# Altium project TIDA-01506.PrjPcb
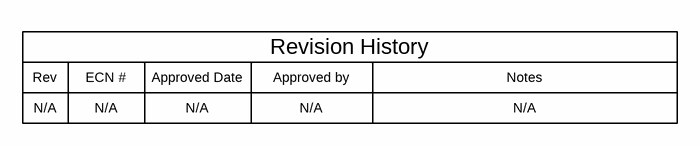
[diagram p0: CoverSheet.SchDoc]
CopyrightYear: 2017; EVM_orderable: N/A; PCB_Layout: Sandeep Tallada; PCB_Rev: E1; PRJ_Customer: Public Release; PRJ_Engineer: Sandeep Tallada; PRJ_Number: TIDA-01506; PRJ_Title: Reference Design for Automotive, Proportional-Solenoid Current Sensor; SCH_Rev: E1; TechSupport: http://www.ti.com/support; TID: TIDA-01506
3 sheets, 35 parts. Net scope: flat (ports and power ports of the same name join across sheets).
Board file: TIDA-01506_PCBLayout.PcbDoc
Sheets:
  CoverSheet.SchDoc
  EVM_Hardware.SchDoc
  TIDA-01506_Schematics.SchDoc

## Sheet CoverSheet.SchDoc
size 431 x 279 mm; Date: Not shown in title block; ApprovedBy: Not shown in title block; CheckedBy: Not shown in title block; Author: Not shown in title block; CompanyName: Not shown in title block; Engineer: Not shown in title block; Organization: Not shown in title block; Address1: Not shown in title block; Address2: Not shown in title block; Address3: Not shown in title block; Address4: Not shown in title block; DocumentNumber: 1; Revision: Use project parameter SCH_Rev; SheetNumber: 1; SheetTotal: 3; PageSetup: Record=PageOptions¦CenterHorizontal=True¦CenterVertical=True¦PrintScale=1.00¦XCorrection=1.00¦YCorrection=1.00¦PrintKind=0¦BorderSize=5000000¦LeftOffset=0¦BottomOffset=0¦Orientation=2¦PaperLength=1000¦PaperWidth=1000¦Scale=100¦PaperSource=15¦PrintQuality=600¦MediaType=1¦DitherType=10¦PaperKind=Letter¦PrintScaleMode=1

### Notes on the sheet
- Rev
- N/A
- ECN #
- Approved Date
- Approved by
- Revision History
- Notes

## Sheet EVM_Hardware.SchDoc
size 431 x 279 mm; Date: Not shown in title block; ApprovedBy: Not shown in title block; CheckedBy: Not shown in title block; Author: Not shown in title block; CompanyName: Not shown in title block; Engineer: Not shown in title block; Organization: Not shown in title block; Address1: Not shown in title block; Address2: Not shown in title block; Address3: Not shown in title block; Address4: Not shown in title block; DocumentNumber: 1; Revision: Use project parameter SCH_Rev; SheetNumber: 3; SheetTotal: 3; PageSetup: Record=PageOptions¦CenterHorizontal=True¦CenterVertical=True¦PrintScale=1.00¦XCorrection=1.00¦YCorrection=1.00¦PrintKind=0¦BorderSize=5000000¦LeftOffset=0¦BottomOffset=0¦Orientation=2¦PaperLength=1000¦PaperWidth=1000¦Scale=100¦PaperSource=15¦PrintQuality=600¦MediaType=1¦DitherType=10¦PaperKind=Letter¦PrintScaleMode=1
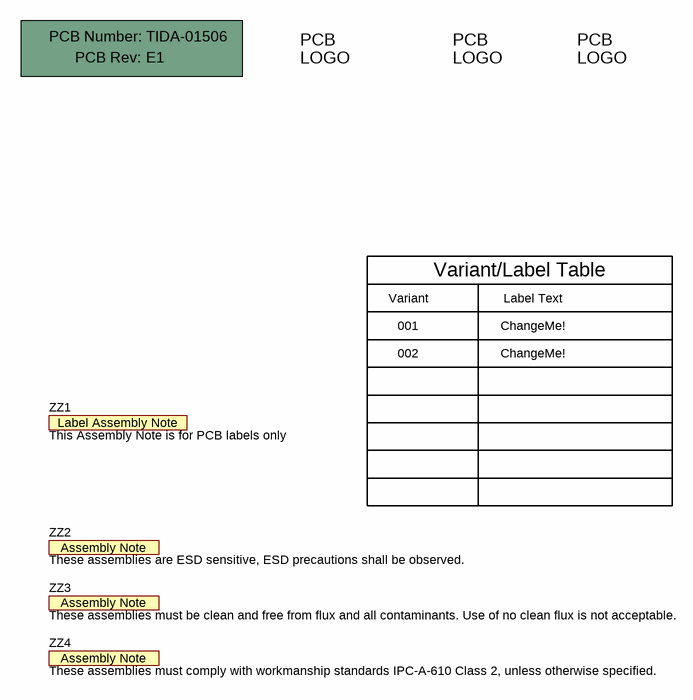
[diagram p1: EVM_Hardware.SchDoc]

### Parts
!PCB  Printed Circuit Board  (value not drawn)  (mechanical)
Logo1  Texas Instruments  [TI_Symbol_Overlay_Small]  (value not drawn)  (no BOM)
Logo2  Pb-Free Symbol  [Pb-Free_Overlay_Small]  (value not drawn)  (no BOM)
Logo3  FCC disclaimer  [FCC_disclaimer]  (value not drawn)  (no BOM)
ZZ1  This Assembly Note is for PCB labels only  [AssemblyNoteLabel]  (no BOM)
ZZ2  These assemblies are ESD sensitive, ESD precautions shall be observed.  [AssemblyNote]  (no BOM)
ZZ3  These assemblies must be clean and free from flux and all contaminants. Use of no clean flux is not acceptable.  [AssemblyNote]  (no BOM)
ZZ4  These assemblies must comply with workmanship standards IPC-A-610 Class 2, unless otherwise specified.  [AssemblyNote]  (no BOM)

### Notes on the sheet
- Variant
- Variant/Label Table
- Label Text
- 001
- 002
- ChangeMe!

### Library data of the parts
!PCB = PCB: Manufacturer: Any; PartNumber: TIDA-01506; SymbolCreator: a0412235
Logo1 = TI_Logo: Texas Instrument Corporate Signature; SymbolCreator: a0412235
Logo2 = Pb-Free: SymbolCreator: a0412235
Logo3 = FCC_disclaimer: SymbolCreator: a0412235
ZZ1 = AssemblyNoteLabel: SymbolCreator: a0412235
ZZ2-ZZ4 = AssemblyNote: SymbolCreator: codlsc

## Sheet TIDA-01506_Schematics.SchDoc
size 431 x 279 mm; Date: Not shown in title block; ApprovedBy: Not shown in title block; CheckedBy: Not shown in title block; Author: Not shown in title block; CompanyName: Not shown in title block; DrawnBy: Sandeep Tallada; Engineer: Sandeep Tallada; Organization: Not shown in title block; Address1: Not shown in title block; Address2: Not shown in title block; Address3: Not shown in title block; Address4: Not shown in title block; DocumentNumber: 1; Revision: Use project parameter SCH_Rev; SheetNumber: 2; SheetTotal: 3; PageSetup: Record=PageOptions¦CenterHorizontal=True¦CenterVertical=True¦PrintScale=0.62¦XCorrection=1.00¦YCorrection=1.00¦PrintKind=0¦BorderSize=5000000¦LeftOffset=0¦BottomOffset=0¦Orientation=2¦PaperLength=2794¦PaperWidth=2159¦Scale=100¦PaperSource=7¦PrintQuality=600¦MediaType=1¦DitherType=10¦PrintScaleMode=1¦PaperKind=8 1/2x11¦PaperIndex=1
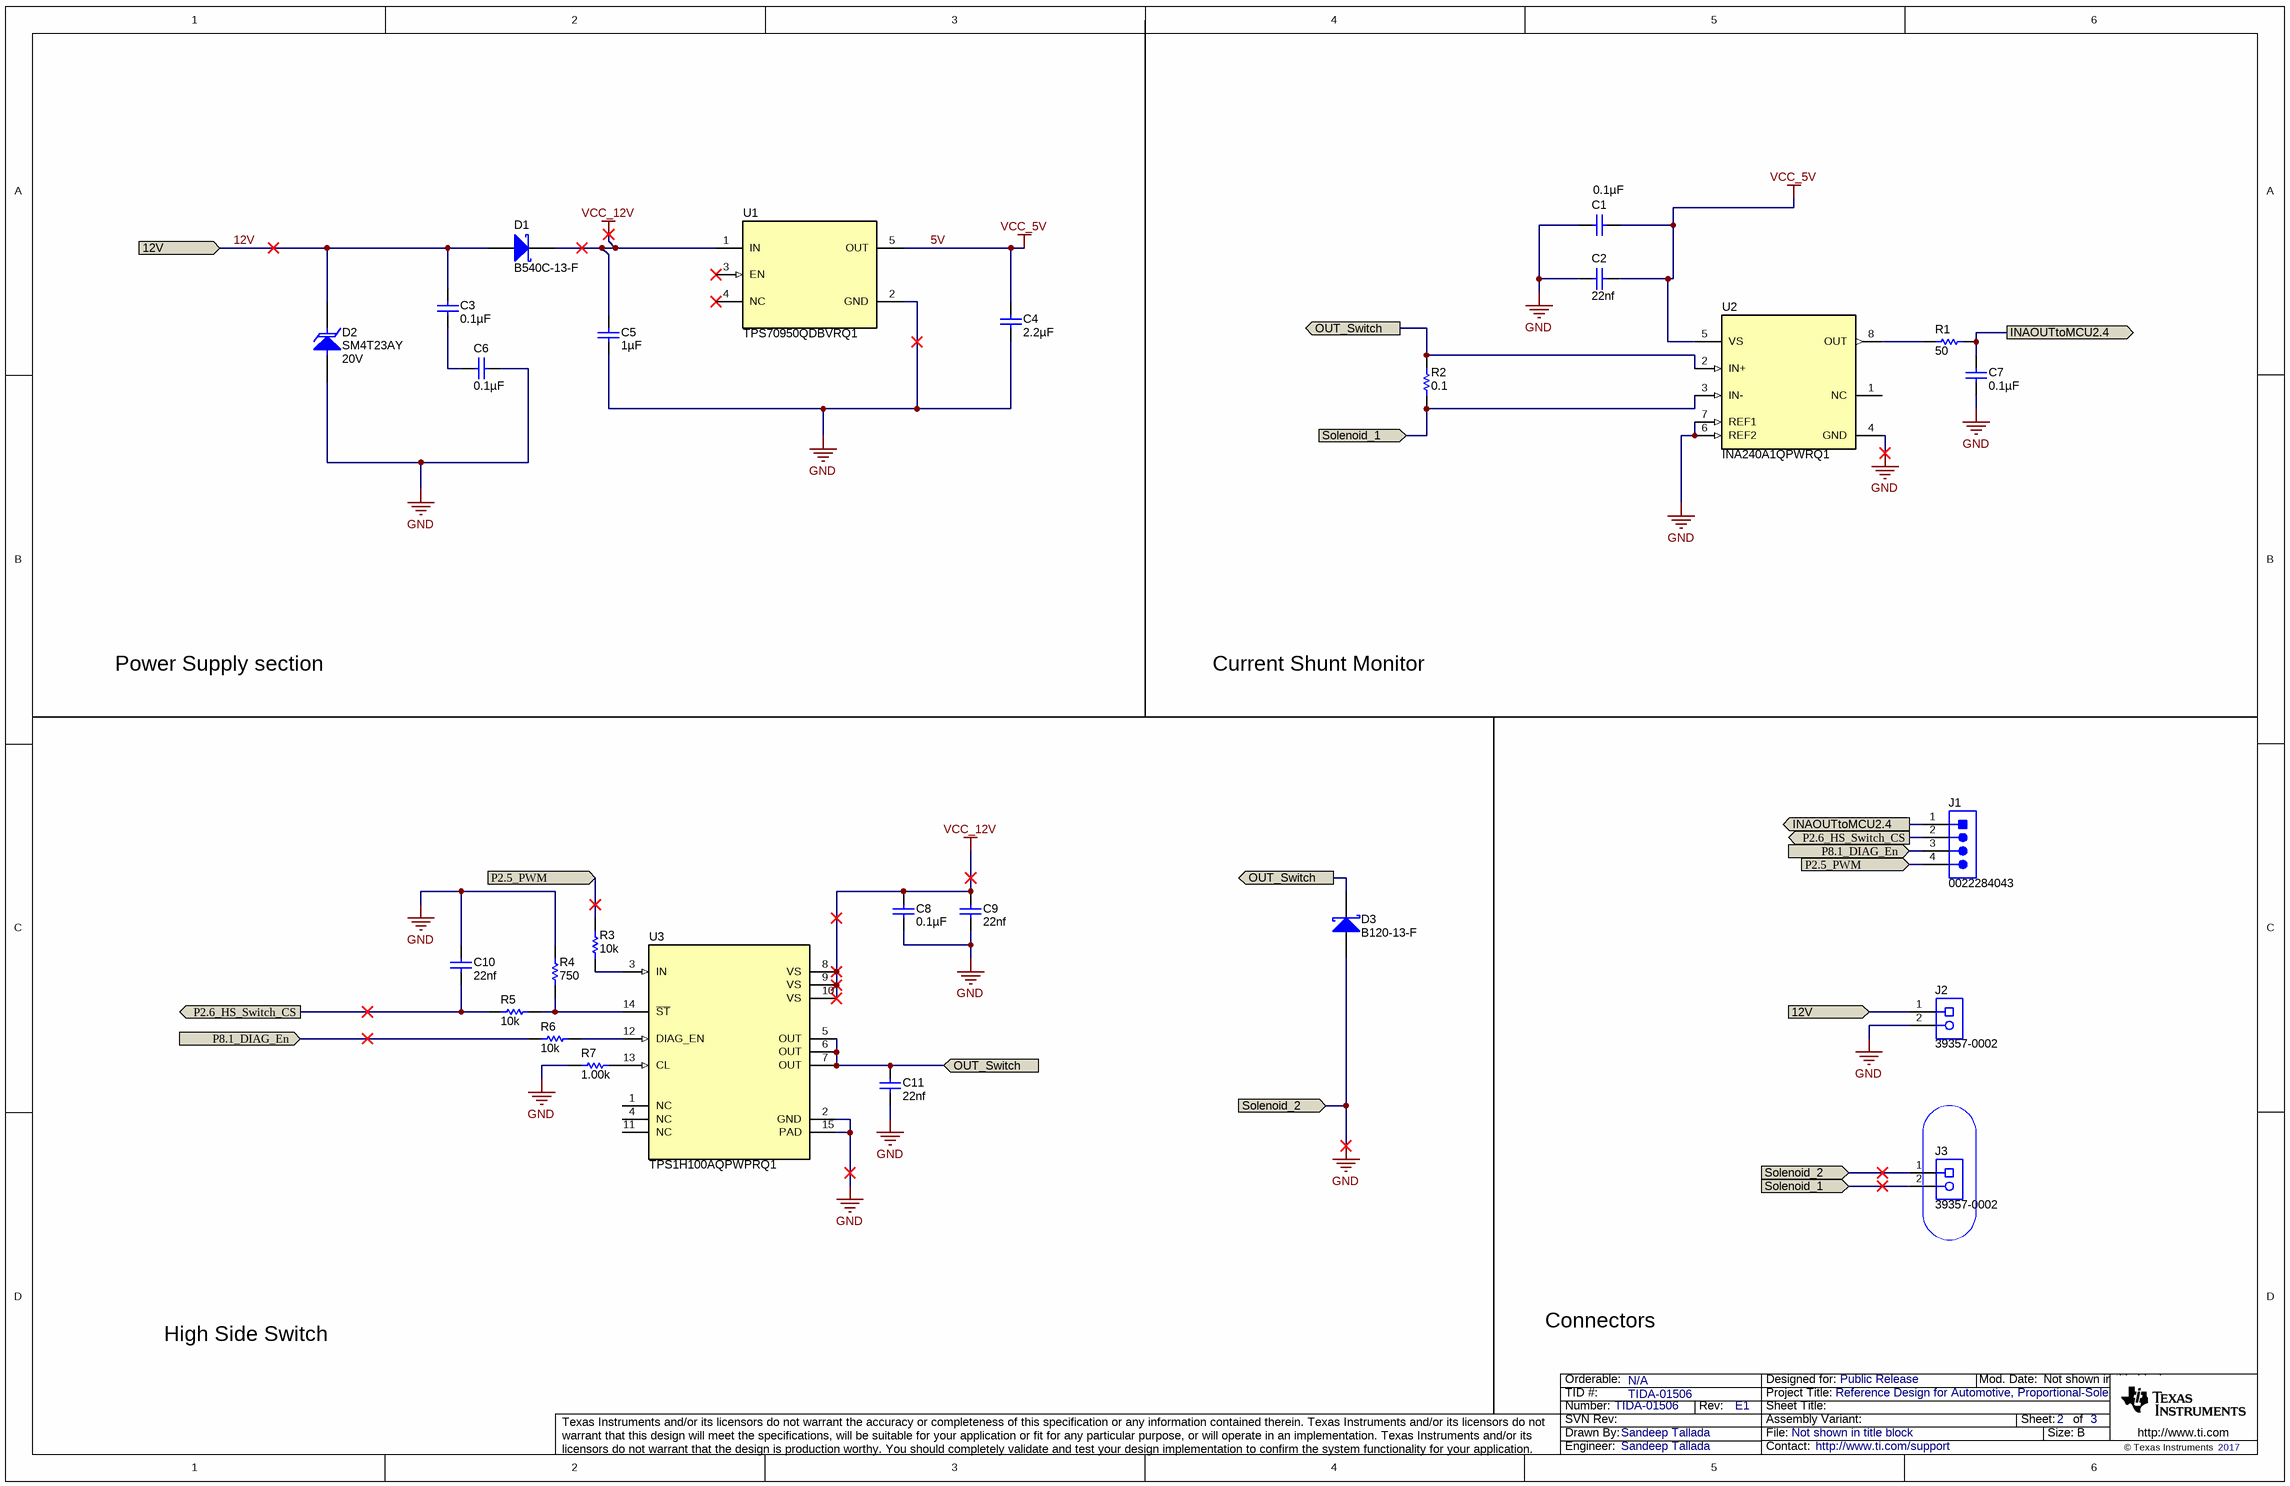
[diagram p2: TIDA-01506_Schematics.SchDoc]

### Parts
C1  ValueDisplayed: 0.1µF  [0603S]  (hidden comment: 0603YC104JAT2A)
C2  ValueDisplayed: 22nf  [0603S]  (hidden comment: CGA3E1X7R1V105K080AC)
C3  ValueDisplayed: 0.1µF  [0603S]  (hidden comment: GRM188R72A104KA35J)
C4  ValueDisplayed: 2.2µF  [0603S]  (hidden comment: GRM188Z71C225KE43)
C5  ValueDisplayed: 1µF  [0603S]  (hidden comment: CGA3E1X7R1V105K080AC)
C6  ValueDisplayed: 0.1µF  [0603S]  (hidden comment: GRM188R72A104KA35J)
C7  ValueDisplayed: 0.1µF  [0603S]  (hidden comment: 0603YC104JAT2A)
C8  ValueDisplayed: 0.1µF  [0603S]  (hidden comment: 0603YC104JAT2A)
C9  ValueDisplayed: 22nf  [0603S]  (hidden comment: CGA3E1X7R1V105K080AC)
C10  ValueDisplayed: 22nf  [0603S]  (hidden comment: CGA3E1X7R1V105K080AC)
C11  ValueDisplayed: 22nf  [0603S]  (hidden comment: CGA3E1X7R1V105K080AC)
D1  B540C-13-F  [SMC]
D2  SM4T23AY  value 20V  [SMA]
D3  B120-13-F  [SMA]
J1  0022284043  [Molex_0022284043]
J2  39357-0002  [Molex_39357-0002]
J3  39357-0002  [Molex_39357-0002]
R1  ValueDisplayed: 50  [0603S]  (hidden comment: FC0603E50R0BTBST1)
R2  value 0.1  [1206]  (hidden comment: UR73V2BTTDR100F)
R3  ValueDisplayed: 10k  [0603S]  (hidden comment: CRCW060310K0JNEA)
R4  ValueDisplayed: 750  [0805]  (hidden comment: CRCW0805750RJNEA)
R5  ValueDisplayed: 10k  [0603S]  (hidden comment: CRCW060310K0JNEA)
R6  ValueDisplayed: 10k  [0603S]  (hidden comment: CRCW060310K0JNEA)
R7  ValueDisplayed: 1.00k  [0805M]  (hidden comment: CRCW08051K00FKEA)
U1  TPS70950QDBVRQ1  [DBV0005A_N]
U2  INA240A1QPWRQ1  [PW0008A_N]
U3  TPS1H100AQPWPRQ1  [PWP0014F_N]

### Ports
12V (in), INAOUTtoMCU2.4 (out), OUT_Switch, P2.5_PWM (in), P2.6_HS_Switch_CS, P8.1_DIAG_En (in), Solenoid_1 (in), Solenoid_2 (in)

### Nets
5V: C1.2 C2.2 C4.1 U1.5(OUT) U2.5(VS)  [also labelled VCC_5V]
GND: C1.1 C2.1 C4.2 C5.1 C6.2 C7.2 C8.1 C9.1 C10.2 C11.1 D2.2(A) D3.2(A) J2.2 J3.1 R4.2 R7.1 U1.2(GND) U2.4(GND) U2.6(REF2) U2.7(REF1) U3.2(GND) U3.15(PAD) ; port Solenoid_2
VCC_12V: C5.2 C8.2 C9.2 D1.1(K) U1.1(IN) U3.8(VS) U3.9(VS) U3.10(VS)
12V: C3.1 D1.2(A) D2.1(K) J2.1 ; port 12V
INAOUTtoMCU2.4: C7.1 J1.1 R1.2 ; port INAOUTtoMCU2.4
OUT_Switch: C11.2 D3.1(K) R2.2 U2.2(IN+) U3.5(OUT) U3.6(OUT) U3.7(OUT) ; port OUT_Switch
P2.5_PWM: J1.4 R3.2 ; port P2.5_PWM
P2.6_HS_Switch_CS: C10.1 J1.2 R5.1 ; port P2.6_HS_Switch_CS
P8.1_DIAG_En: J1.3 R6.1 ; port P8.1_DIAG_En
Solenoid_1: J3.2 R2.1 U2.3(IN-) ; port Solenoid_1
NetC3_2: C3.2 C6.1
NetR1_1: R1.1 U2.8(OUT)
NetR3_1: R3.1 U3.3(IN)
NetR4_1: R4.1 R5.2 U3.14(~{ST})
NetR6_2: R6.2 U3.12(DIAG_EN)
NetR7_2: R7.2 U3.13(CL)

Not connected (* = marked no-connect by the designer): U1 3(EN)* 4(NC)*; U2 1(NC); U3 1(NC) 4(NC) 11(NC)

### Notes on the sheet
- Power Supply section
- Current Shunt Monitor
- High Side Switch
- Connectors

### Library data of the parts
C1 C7 C8 = 0603YC104JAT2A: CAP, CERM, 0.1 µF, 16 V, +/- 5%, X7R, 0603; Manufacturer: AVX; Polarized: N; CompType: Capacitor; Value: 0.1uF; U/M: EA; Cap_F: 0.0000001; Tolerance_%: 5; ESR_ohm: 0.039; Value1: 0.039 ohm; VDC_V: 16; Value2: 16V; TaMin_C: -55; TaMax_C: 125; Cap_Case: 0603; AEC Category: Q200
C2 C5 C9-C11 = CGA3E1X7R1V105K080AC: CAP, CERM, 1 µF, 35 V, +/- 10%, X7R, AEC-Q200 Grade 1, 0603; Manufacturer: TDK; Polarized: N; CompType: Capacitor; Value: 1uF; U/M: EA; Cap_F: 0.000001; Tolerance_%: 10; ESR_ohm: 0.005522; Value1: 0.005522 ohm; VDC_V: 35; Value2: 35V; IRMS_A: 2.21617; TaMin_C: -55; TaMax_C: 125; Cap_Case: 0603; SizeArea_mm2: 1.28; SizeAreaWB_mm2: 4.68; SizeX_mm: 1.6; SizeY_mm: 0.8; SizeZ_mm: 1; AEC Category: Q200; AEC Qualified: Y
C3 C6 = GRM188R72A104KA35J: CAP, CERM, 0.1 µF, 100 V, +/- 10%, X7R, 0603; Manufacturer: MuRata; Polarized: N; CompType: Capacitor; Value: 0.1uF; U/M: EA; Cap_F: 0.0000001; Tolerance_%: 10; Value1: Unknown; VDC_V: 100; Value2: 100V; TaMin_C: -55; TaMax_C: 125; Cap_Case: 0603; SizeArea_mm2: 1.28; SizeAreaWB_mm2: 4.68; SizeX_mm: 1.6; SizeY_mm: 0.8; SizeZ_mm: 1; AEC Category: Q200
C4 = GRM188Z71C225KE43: CAP, CERM, 2.2 µF, 16 V, +/- 10%, X7R, 0603; Manufacturer: MuRata; Polarized: N; CompType: Capacitor; Value: 2.2uF; U/M: EA; Cap_F: 0.0000022; Tolerance_%: 10; Value1: Unknown; VDC_V: 16; Value2: 16V; TaMin_C: -55; TaMax_C: 125; Cap_Case: 0603; AEC Category: Q200
D1 = B540C-13-F: Diode, Schottky, 40 V, 5 A, SMC; Manufacturer: Diodes Inc.; U/M: EA; Vf_V: 0.55; Value: 40V; Value1: 5A; Value2: 0.55V; Io_A: 5; Vr_V: 40; TJmax_C: 125; RJC_CperW: 10; SizeAreaWB_mm2: 83.2686; SizeArea_mm2: 50.5686; SizeX_mm: 8.13; SizeY_mm: 6.22; SizeZ_mm: 2.6; AEC Category: Q101
D2 = CMP-0078853-1: Diode, TVS, Uni, 20 V, 42.8 Vc, AEC-Q101, SMA; Manufacturer: STMicroelectronics; SizeAreaWB_mm2: 37.3428; SizeZ_mm: 2.87; SizeX_mm: 5.59; SizeY_mm: 2.92; SizeArea_mm2: 16.3228; AEC Qualified: Y; AEC Category: Q101
D3 = B120-13-F: Diode, Schottky, 20 V, 1 A, SMA; Manufacturer: Diodes Inc.; U/M: EA; Vf_V: 0.5; Value: 20V; Value1: 1A; Value2: 0.5V; Io_A: 1; Vr_V: 20; TJmax_C: 150; SizeAreaWB_mm2: 37.3428; SizeArea_mm2: 16.3228; SizeX_mm: 5.59; SizeY_mm: 2.92; SizeZ_mm: 2.87; AEC Category: Q101
J1 = 0022284043: Header, 2.54mm, 4x1, Tin, TH; Manufacturer: Molex; SymbolCreator: a0412235; Pitch_mm: 2.54; Gender: Male; Shrouded: N; Row_Count: 1; Current_A: 4; Voltage_V: 250; Cert_UL: Y
J2 J3 = 39357-0002: Terminal Block, 3.5 mm, 2x1, Tin, TH; Manufacturer: Molex; SymbolCreator: a0412235
R1 = FC0603E50R0BTBST1: RES, 50, 0.1%, 0.125 W, 0603; Manufacturer: Vishay Thin Film; CompType: Resistor; Value: 50; Value_Code: 50R0; Tolerance_%: 0.1; Power_W: 0.125; Value2: 0.125W; TempCo: 25 ppm/C; SizeArea_mm2: 1.28; SizeX_mm: 1.6; SizeY_mm: 0.8; SizeZ_mm: 1; U/M: EA; AEC Category: Q200; AEC Qualified: N
R2 = CMP-0074897-1: RES, 0.1, 1%, 0.5 W, AEC-Q200 Grade 1, 1206; Manufacturer: KOA Speer; Power_W: 500mW; TempCo: 100 ppm/C; Value_Code: R100; U/M: EA; EIA_Code: E96; Res_ohm: 1d; SizeX_mm: 3.2; SizeY_mm: 1.6; SizeZ_mm: 1.35; Value2: 0.5W; SizeArea_mm2: 5.12; CompType: Resistor; AEC Qualified: Y; AEC Grade: 1; AEC Category: Q200
R3 R5 R6 = CRCW060310K0JNEA: RES, 10 k, 5%, 0.1 W, 0603; Manufacturer: Vishay-Dale; CompType: Resistor; Value: 10k; Res_ohm: 10000; Value_Code: 10k0; Tolerance_%: 5; Power_W: 0.1; Value2: 0.1W; VDC_V: 75; TempCo: 200 ppm/C; SizeArea_mm2: 1.28; SizeX_mm: 1.6; SizeY_mm: 0.8; SizeZ_mm: 1; EIA_Code: E24; U/M: EA; AEC Category: Q200
R4 = CRCW0805750RJNEA: RES, 750, 5%, 0.125 W, 0805; Manufacturer: Vishay-Dale; CompType: Resistor; Value: 750; Value_Code: 750R; Tolerance_%: 5; Power_W: 0.125; Value2: 0.125W; VDC_V: 150; TempCo: 200 ppm/C; SizeArea_mm2: 2.5; SizeX_mm: 2; SizeY_mm: 1.25; SizeZ_mm: 1.45; EIA_Code: E24; U/M: EA; AEC Category: Q200
R7 = CRCW08051K00FKEA: RES, 1.00 k, 1%, 0.125 W, 0805; Manufacturer: Vishay-Dale; CompType: Resistor; Value: 1.00k; Res_ohm: 1000; Value_Code: 1k00; Tolerance_%: 1; Power_W: 0.125; Value2: 0.125W; VDC_V: 150; TempCo: 100 ppm/C; SizeArea_mm2: 2.5; SizeX_mm: 2; SizeY_mm: 1.25; SizeZ_mm: 1.45; EIA_Code: E96; U/M: EA; AEC Category: Q200
U1 = CMP-0079136-1: 150-mA, 30-V, Ultra-Low IQ, Wide Input LDO with Reverse Current Protection for Automotive, DBV0005A (SOT-23-5); Alternate Manufacturer: Texas Instruments; SizeAreaWB_mm2: 14.82; SizeZ_mm: 1.45; SizeX_mm: 2.8; SizeY_mm: 2.9; SizeArea_mm2: 8.12; CompType: IC; AEC Qualified: Y; AEC Category: Q200
U2 = CMP-0077375-1: Automotive, Wide Common-Mode Range, High- and Low-Side, Bidirectional, Zero-Drift, Current-Sense Amplifier With Enhanced PWM Rejection, PW0008A (TSSOP-8); Manufacturer: Texas Instruments; SizeArea_mm2: 19.2; CompType: IC; SizeAreaWB_mm2: 42; SizeY_mm: 3; SizeZ_mm: 1.2; U/M: EA; SizeX_mm: 6.4
U3 = TPS1H100AQPWPRQ1: 40V/100mOhm Single Channel Smart High Side Switch, PWP0014F (TSSOP-14); Manufacturer: Texas Instruments; SymbolCreator: a0411947; SizeArea_mm2: 32; SizeAreaWB_mm2: 58.8; SizeX_mm: 6.4; SizeY_mm: 5; SizeZ_mm: 1.2; CompType: IC; U/M: EA

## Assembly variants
001: not fitted FID1 FID2 FID3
